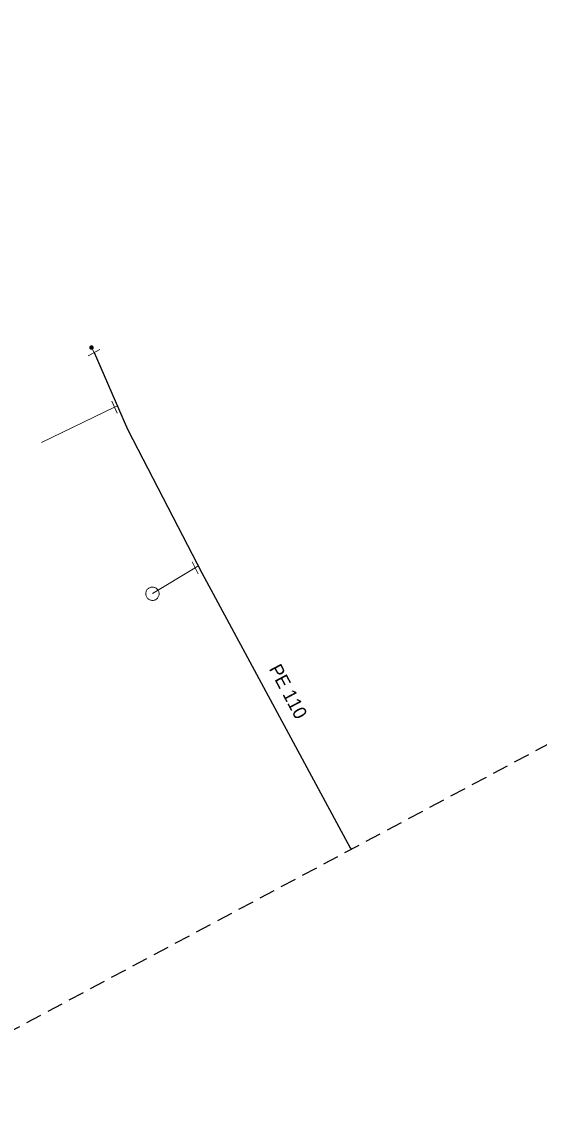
# Model space of a CAD drawing. Extents: x -779496 to -779026, y -977086 to -976624.
# Drawn here: x -779290.8 to -779252, y -977004.5 to -976922.6 of the extents above; entities that cross this region are included whole.
import ezdxf

# ---------------------------------------------------------------- set-up
doc = ezdxf.new("R2010")
doc.units = 0
doc.header["$LTSCALE"] = 0.4
doc.linetypes.add('MEDIUM_DASHED', pattern=[4.5, 3, -1.5])
for name, color, linetype, lineweight in [('1', 7, 'MEDIUM_DASHED', 25), ('13', 7, 'Continuous', 13), ('14', 7, 'Continuous', 13), ('17', 7, 'Continuous', 25), ('23', 7, 'Continuous', 13), ('34', 7, 'Continuous', 13), ('9', 7, 'Continuous', 13)]:
    doc.layers.add(name, color=color, linetype=linetype, lineweight=lineweight)

msp = doc.modelspace()

# ---------------------------------------------------------------- linework, layer by layer
at = {"layer": '1'}
msp.add_lwpolyline([(-779144.045, -976624.23), (-779025.876, -976692.559), (-779211.57, -976955.425), (-779456.75, -977086.455), (-779496.14, -976963.463), (-779320.896, -976797.866)], close=True, dxfattribs=at)
at = {"layer": '13'}
for p, q in [((-779289.3, -976954.098), (-779283.82, -976951.46)), ((-779280.98, -976965.399), (-779277.789, -976963.489))]:
    msp.add_line(p, q, dxfattribs=at)
at = {"layer": '14'}
for p, q in [((-779285.359, -976947.379), (-779285.548, -976946.997)), ((-779283.608, -976951.372), (-779283.82, -976951.46)), ((-779277.557, -976963.342), (-779277.789, -976963.489))]:
    msp.add_line(p, q, dxfattribs=at)
at = {"layer": '17'}
msp.add_lwpolyline([(-779285.359, -976947.379), (-779283.018, -976952.708), (-779282.82, -976953.16), (-779279.075, -976960.405), (-779277.289, -976963.859), (-779266.18, -976984.44), (-779266.099, -976984.567)], dxfattribs=at)
at = {"layer": '23'}
for points in [[(-779280.561, -976965.169), (-779280.591, -976965.125), (-779280.625, -976965.085), (-779280.663, -976965.05), (-779280.705, -976965.018), (-779280.749, -976964.991), (-779280.797, -976964.968), (-779280.846, -976964.951), (-779280.897, -976964.939), (-779280.949, -976964.932), (-779281.001, -976964.931), (-779281.054, -976964.934), (-779281.106, -976964.944), (-779281.155, -976964.959), (-779281.203, -976964.979), (-779281.249, -976965.003), (-779281.293, -976965.034), (-779281.332, -976965.067), (-779281.369, -976965.106), (-779281.4, -976965.146), (-779281.428, -976965.191), (-779281.45, -976965.24), (-779281.467, -976965.289), (-779281.479, -976965.34), (-779281.487, -976965.392), (-779281.488, -976965.443), (-779281.483, -976965.496), (-779281.473, -976965.547), (-779281.458, -976965.597), (-779281.438, -976965.645), (-779281.414, -976965.692), (-779281.384, -976965.735), (-779281.35, -976965.775), (-779281.312, -976965.811), (-779281.271, -976965.843), (-779281.226, -976965.868), (-779281.179, -976965.891), (-779281.129, -976965.909), (-779281.078, -976965.922), (-779281.026, -976965.928)], [(-779281.369, -976965.106), (-779281.4, -976965.146), (-779281.428, -976965.191), (-779281.45, -976965.24), (-779281.467, -976965.289), (-779281.479, -976965.34), (-779281.487, -976965.392), (-779281.488, -976965.443), (-779281.483, -976965.496), (-779281.473, -976965.547), (-779281.458, -976965.597), (-779281.438, -976965.645), (-779281.414, -976965.692), (-779281.384, -976965.735), (-779281.35, -976965.775), (-779281.312, -976965.811), (-779281.271, -976965.843), (-779281.226, -976965.868), (-779281.179, -976965.891), (-779281.129, -976965.909), (-779281.078, -976965.922), (-779281.026, -976965.928), (-779280.975, -976965.93), (-779280.922, -976965.925), (-779280.871, -976965.917), (-779280.82, -976965.9), (-779280.773, -976965.88), (-779280.727, -976965.856), (-779280.684, -976965.826), (-779280.644, -976965.792), (-779280.607, -976965.754), (-779280.576, -976965.712), (-779280.548, -976965.668), (-779280.526, -976965.622), (-779280.509, -976965.571), (-779280.496, -976965.521), (-779280.49, -976965.469), (-779280.488, -976965.416), (-779280.492, -976965.364), (-779280.502, -976965.313)], [(-779281.026, -976965.928), (-779280.975, -976965.93), (-779280.922, -976965.925), (-779280.871, -976965.917), (-779280.82, -976965.9), (-779280.773, -976965.88), (-779280.727, -976965.856), (-779280.684, -976965.826), (-779280.644, -976965.792), (-779280.607, -976965.754), (-779280.576, -976965.712), (-779280.548, -976965.668), (-779280.526, -976965.622), (-779280.509, -976965.571), (-779280.496, -976965.521), (-779280.49, -976965.469), (-779280.488, -976965.416), (-779280.492, -976965.364), (-779280.502, -976965.313), (-779280.518, -976965.263), (-779280.537, -976965.215), (-779280.561, -976965.169), (-779280.591, -976965.125), (-779280.625, -976965.085), (-779280.663, -976965.05), (-779280.705, -976965.018), (-779280.749, -976964.991), (-779280.797, -976964.968), (-779280.846, -976964.951), (-779280.897, -976964.939), (-779280.949, -976964.932), (-779281.001, -976964.931), (-779281.054, -976964.934), (-779281.106, -976964.944), (-779281.155, -976964.959), (-779281.203, -976964.979), (-779281.249, -976965.003), (-779281.293, -976965.034), (-779281.332, -976965.067), (-779281.369, -976965.106)], [(-779280.502, -976965.313), (-779280.518, -976965.263), (-779280.537, -976965.215), (-779280.561, -976965.169)]]:
    msp.add_lwpolyline(points, dxfattribs=at)
at = {"layer": '34'}
for p, q in [((-779284.915, -976947.148), (-779285.803, -976947.608)), ((-779283.618, -976951.917), (-779284.02, -976951.002)), ((-779277.559, -976963.932), (-779278.018, -976963.044))]:
    msp.add_line(p, q, dxfattribs=at)
at = {"layer": '9'}
for points in [[(-779285.674, -976946.997), (-779285.674, -976947.01), (-779285.671, -976947.023), (-779285.669, -976947.036), (-779285.664, -976947.048), (-779285.657, -976947.06), (-779285.651, -976947.071), (-779285.642, -976947.081), (-779285.632, -976947.091), (-779285.622, -976947.099), (-779285.612, -976947.106), (-779285.6, -976947.112), (-779285.588, -976947.117), (-779285.575, -976947.12), (-779285.561, -976947.122), (-779285.549, -976947.124), (-779285.536, -976947.123), (-779285.522, -976947.121), (-779285.51, -976947.118), (-779285.497, -976947.113), (-779285.485, -976947.107), (-779285.475, -976947.1), (-779285.465, -976947.092), (-779285.455, -976947.082), (-779285.446, -976947.072), (-779285.44, -976947.061), (-779285.434, -976947.049), (-779285.429, -976947.037), (-779285.426, -976947.024), (-779285.424, -976947.011), (-779285.421, -976946.998), (-779285.423, -976946.985), (-779285.424, -976946.972), (-779285.428, -976946.959), (-779285.433, -976946.947), (-779285.438, -976946.935), (-779285.446, -976946.924), (-779285.453, -976946.914), (-779285.463, -976946.904), (-779285.473, -976946.896), (-779285.485, -976946.889), (-779285.497, -976946.883), (-779285.509, -976946.878), (-779285.522, -976946.875), (-779285.534, -976946.873), (-779285.548, -976946.872), (-779285.561, -976946.872), (-779285.573, -976946.874), (-779285.587, -976946.877), (-779285.598, -976946.882), (-779285.61, -976946.888), (-779285.622, -976946.895), (-779285.632, -976946.903), (-779285.642, -976946.913), (-779285.649, -976946.923), (-779285.657, -976946.934), (-779285.663, -976946.946), (-779285.668, -976946.958), (-779285.671, -976946.971), (-779285.673, -976946.984)], [(-779285.654, -976946.997), (-779285.654, -976947.008), (-779285.652, -976947.019), (-779285.649, -976947.03), (-779285.646, -976947.04), (-779285.641, -976947.05), (-779285.635, -976947.059), (-779285.627, -976947.068), (-779285.62, -976947.076), (-779285.61, -976947.083), (-779285.602, -976947.089), (-779285.592, -976947.094), (-779285.581, -976947.098), (-779285.571, -976947.101), (-779285.559, -976947.104), (-779285.549, -976947.104), (-779285.538, -976947.104), (-779285.527, -976947.102), (-779285.516, -976947.099), (-779285.505, -976947.095), (-779285.495, -976947.09), (-779285.487, -976947.084), (-779285.478, -976947.077), (-779285.47, -976947.069), (-779285.463, -976947.06), (-779285.456, -976947.051), (-779285.451, -976947.041), (-779285.448, -976947.031), (-779285.445, -976947.02), (-779285.443, -976947.009), (-779285.441, -976946.998), (-779285.441, -976946.987), (-779285.443, -976946.976), (-779285.446, -976946.965), (-779285.451, -976946.955), (-779285.456, -976946.945), (-779285.462, -976946.936), (-779285.468, -976946.927), (-779285.477, -976946.919), (-779285.485, -976946.912), (-779285.495, -976946.906), (-779285.505, -976946.901), (-779285.514, -976946.897), (-779285.526, -976946.894), (-779285.536, -976946.892), (-779285.548, -976946.892), (-779285.559, -976946.891), (-779285.57, -976946.893), (-779285.581, -976946.896), (-779285.59, -976946.9), (-779285.6, -976946.905), (-779285.61, -976946.911), (-779285.619, -976946.918), (-779285.627, -976946.926), (-779285.634, -976946.935), (-779285.639, -976946.944), (-779285.644, -976946.954), (-779285.649, -976946.964), (-779285.652, -976946.975), (-779285.654, -976946.986)], [(-779285.635, -976946.997), (-779285.635, -976947.006), (-779285.634, -976947.015), (-779285.63, -976947.024), (-779285.627, -976947.032), (-779285.624, -976947.04), (-779285.619, -976947.048), (-779285.612, -976947.055), (-779285.607, -976947.061), (-779285.6, -976947.067), (-779285.592, -976947.072), (-779285.583, -976947.076), (-779285.576, -976947.079), (-779285.566, -976947.082), (-779285.558, -976947.083), (-779285.549, -976947.085), (-779285.539, -976947.084), (-779285.531, -976947.083), (-779285.522, -976947.08), (-779285.514, -976947.077), (-779285.505, -976947.073), (-779285.497, -976947.068), (-779285.49, -976947.062), (-779285.485, -976947.056), (-779285.478, -976947.049), (-779285.473, -976947.041), (-779285.47, -976947.033), (-779285.467, -976947.025), (-779285.463, -976947.016), (-779285.463, -976947.007), (-779285.46, -976946.998), (-779285.462, -976946.989), (-779285.463, -976946.98), (-779285.465, -976946.971), (-779285.468, -976946.963), (-779285.473, -976946.955), (-779285.478, -976946.947), (-779285.483, -976946.94), (-779285.49, -976946.934), (-779285.497, -976946.928), (-779285.505, -976946.923), (-779285.512, -976946.919), (-779285.521, -976946.916), (-779285.529, -976946.913), (-779285.539, -976946.912), (-779285.548, -976946.911), (-779285.556, -976946.911), (-779285.566, -976946.912), (-779285.575, -976946.915), (-779285.583, -976946.918), (-779285.59, -976946.922), (-779285.598, -976946.927), (-779285.605, -976946.933), (-779285.612, -976946.939), (-779285.617, -976946.946), (-779285.622, -976946.954), (-779285.627, -976946.962), (-779285.63, -976946.97), (-779285.632, -976946.979), (-779285.634, -976946.988)], [(-779285.615, -976946.997), (-779285.615, -976947.004), (-779285.614, -976947.011), (-779285.612, -976947.018), (-779285.61, -976947.024), (-779285.607, -976947.03), (-779285.603, -976947.036), (-779285.598, -976947.042), (-779285.593, -976947.047), (-779285.588, -976947.051), (-779285.581, -976947.055), (-779285.576, -976947.058), (-779285.57, -976947.061), (-779285.563, -976947.062), (-779285.556, -976947.065), (-779285.549, -976947.065), (-779285.541, -976947.065), (-779285.534, -976947.063), (-779285.527, -976947.062), (-779285.522, -976947.059), (-779285.514, -976947.056), (-779285.51, -976947.052), (-779285.504, -976947.048), (-779285.499, -976947.043), (-779285.495, -976947.037), (-779285.49, -976947.031), (-779285.487, -976947.025), (-779285.485, -976947.019), (-779285.483, -976947.012), (-779285.482, -976947.005), (-779285.48, -976946.998), (-779285.48, -976946.991), (-779285.482, -976946.984), (-779285.483, -976946.977), (-779285.487, -976946.971), (-779285.49, -976946.964), (-779285.494, -976946.959), (-779285.497, -976946.953), (-779285.502, -976946.948), (-779285.509, -976946.944), (-779285.514, -976946.94), (-779285.521, -976946.937), (-779285.527, -976946.934), (-779285.534, -976946.932), (-779285.541, -976946.931), (-779285.548, -976946.931), (-779285.554, -976946.931), (-779285.561, -976946.931), (-779285.568, -976946.933), (-779285.575, -976946.936), (-779285.581, -976946.939), (-779285.587, -976946.943), (-779285.593, -976946.947), (-779285.598, -976946.952), (-779285.602, -976946.958), (-779285.605, -976946.963), (-779285.608, -976946.97), (-779285.612, -976946.976), (-779285.612, -976946.983), (-779285.615, -976946.99)], [(-779285.595, -976946.997), (-779285.595, -976947.002), (-779285.595, -976947.007), (-779285.593, -976947.012), (-779285.592, -976947.016), (-779285.59, -976947.021), (-779285.587, -976947.025), (-779285.583, -976947.028), (-779285.58, -976947.032), (-779285.576, -976947.035), (-779285.573, -976947.038), (-779285.568, -976947.04), (-779285.563, -976947.042), (-779285.559, -976947.043), (-779285.554, -976947.045), (-779285.549, -976947.045), (-779285.544, -976947.045), (-779285.539, -976947.044), (-779285.534, -976947.043), (-779285.529, -976947.041), (-779285.524, -976947.039), (-779285.521, -976947.036), (-779285.517, -976947.033), (-779285.514, -976947.029), (-779285.511, -976947.026), (-779285.507, -976947.022), (-779285.505, -976947.017), (-779285.504, -976947.013), (-779285.502, -976947.008), (-779285.502, -976947.003), (-779285.5, -976946.998), (-779285.5, -976946.993), (-779285.502, -976946.988), (-779285.502, -976946.983), (-779285.505, -976946.979), (-779285.507, -976946.974), (-779285.51, -976946.97), (-779285.512, -976946.966), (-779285.516, -976946.963), (-779285.519, -976946.96), (-779285.524, -976946.957), (-779285.529, -976946.955), (-779285.532, -976946.953), (-779285.538, -976946.952), (-779285.543, -976946.951), (-779285.548, -976946.951), (-779285.553, -976946.951), (-779285.558, -976946.952), (-779285.563, -976946.952), (-779285.566, -976946.954), (-779285.571, -976946.956), (-779285.576, -976946.959), (-779285.578, -976946.962), (-779285.583, -976946.965), (-779285.585, -976946.969), (-779285.588, -976946.973), (-779285.59, -976946.978), (-779285.593, -976946.982), (-779285.593, -976946.987), (-779285.595, -976946.992)], [(-779285.575, -976946.997), (-779285.575, -976947), (-779285.576, -976947.003), (-779285.575, -976947.005), (-779285.573, -976947.008), (-779285.573, -976947.011), (-779285.571, -976947.013), (-779285.568, -976947.015), (-779285.566, -976947.017), (-779285.565, -976947.019), (-779285.563, -976947.021), (-779285.559, -976947.023), (-779285.556, -976947.024), (-779285.554, -976947.024), (-779285.551, -976947.025), (-779285.549, -976947.025), (-779285.546, -976947.025), (-779285.543, -976947.025), (-779285.539, -976947.024), (-779285.538, -976947.023), (-779285.534, -976947.022), (-779285.532, -976947.02), (-779285.529, -976947.018), (-779285.527, -976947.016), (-779285.527, -976947.014), (-779285.524, -976947.012), (-779285.524, -976947.009), (-779285.522, -976947.006), (-779285.522, -976947.004), (-779285.521, -976947.001), (-779285.519, -976946.998), (-779285.521, -976946.995), (-779285.521, -976946.992), (-779285.522, -976946.989), (-779285.522, -976946.987), (-779285.524, -976946.984), (-779285.526, -976946.982), (-779285.527, -976946.979), (-779285.529, -976946.977), (-779285.532, -976946.976), (-779285.534, -976946.974), (-779285.536, -976946.973), (-779285.539, -976946.972), (-779285.541, -976946.971), (-779285.544, -976946.971), (-779285.548, -976946.97), (-779285.551, -976946.971), (-779285.554, -976946.97), (-779285.556, -976946.972), (-779285.559, -976946.972), (-779285.561, -976946.973), (-779285.563, -976946.975), (-779285.566, -976946.976), (-779285.568, -976946.978), (-779285.57, -976946.981), (-779285.571, -976946.983), (-779285.573, -976946.986), (-779285.573, -976946.988), (-779285.575, -976946.991), (-779285.575, -976946.994)], [(-779285.556, -976946.997), (-779285.556, -976946.999), (-779285.556, -976946.999), (-779285.554, -976946.999), (-779285.554, -976947.001), (-779285.556, -976947.002), (-779285.554, -976947.002), (-779285.554, -976947.002), (-779285.554, -976947.004), (-779285.554, -976947.004), (-779285.553, -976947.005), (-779285.551, -976947.005), (-779285.551, -976947.005), (-779285.551, -976947.006), (-779285.549, -976947.006), (-779285.549, -976947.006), (-779285.548, -976947.006), (-779285.546, -976947.006), (-779285.546, -976947.005), (-779285.546, -976947.005), (-779285.544, -976947.005), (-779285.544, -976947.004), (-779285.544, -976947.004), (-779285.543, -976947.003), (-779285.543, -976947.003), (-779285.541, -976947.002), (-779285.541, -976947.001), (-779285.539, -976947), (-779285.539, -976947), (-779285.539, -976946.999), (-779285.539, -976946.998), (-779285.539, -976946.997), (-779285.539, -976946.996), (-779285.539, -976946.996), (-779285.541, -976946.995), (-779285.541, -976946.994), (-779285.541, -976946.993), (-779285.541, -976946.993), (-779285.543, -976946.992), (-779285.543, -976946.992), (-779285.544, -976946.991), (-779285.544, -976946.991), (-779285.546, -976946.99), (-779285.546, -976946.99), (-779285.546, -976946.99), (-779285.548, -976946.99), (-779285.549, -976946.99), (-779285.549, -976946.99), (-779285.549, -976946.99), (-779285.551, -976946.991), (-779285.551, -976946.99), (-779285.553, -976946.992), (-779285.553, -976946.992), (-779285.554, -976946.992), (-779285.554, -976946.992), (-779285.554, -976946.994), (-779285.554, -976946.995), (-779285.554, -976946.996), (-779285.556, -976946.996), (-779285.556, -976946.997)]]:
    msp.add_lwpolyline(points, close=True, dxfattribs=at)

# ---------------------------------------------------------------- texts
at = {"layer": '1'}
msp.add_text('PE 110', height=1, rotation=298, dxfattribs=at).set_placement((-779272.292, -976971.041))

doc.saveas('drawing.dxf')
